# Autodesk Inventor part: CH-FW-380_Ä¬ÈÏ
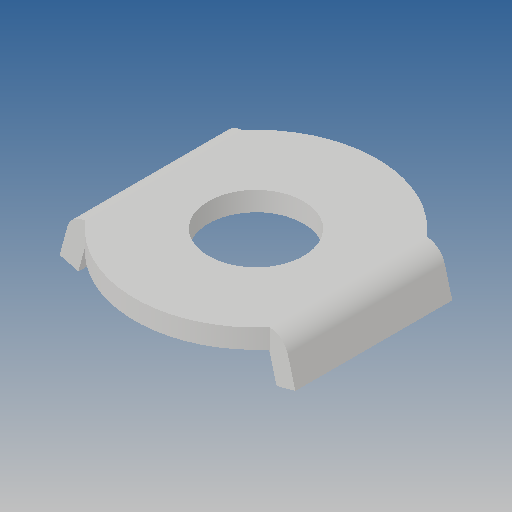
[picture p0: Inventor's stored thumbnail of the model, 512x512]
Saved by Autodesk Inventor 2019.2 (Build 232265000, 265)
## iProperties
Created: 2010-06
Part Number: CH-FW-380_Ä¬ÈÏ
Material: Ogólny
Document SubType Name: Modeling
Designer: CADENGINEERING4
Density: 1 g/cm^3
Appearance: Domyślna
Author: CADENGINEERING4
Revision Number: ÈÎºÎ
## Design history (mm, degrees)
feature "NONE"
node "Bryła1"
